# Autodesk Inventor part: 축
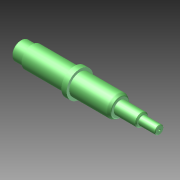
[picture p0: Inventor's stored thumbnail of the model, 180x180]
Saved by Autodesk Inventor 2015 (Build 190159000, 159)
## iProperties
Created: 2024-12
Part Number: 축
Material: 일반
Document SubType Name: Modeling
Designer: 102566
Density: 1 g/cm^3
Appearance: 기본값
Author: 102566
Author: jhkim
Creation Date: 2024-11-28
Sending System: Autodesk Inventor 2025
Preprocessor: ST-DEVELOPER v20
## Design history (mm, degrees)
node "축1"
node "솔리드1"
node "기준1"
